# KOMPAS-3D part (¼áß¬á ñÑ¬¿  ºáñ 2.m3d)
File: created 06.04.2016 12:01:11, last saved 22.07.2016 15:59:11.
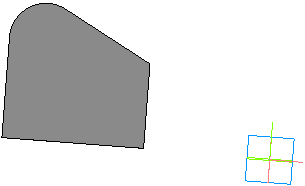
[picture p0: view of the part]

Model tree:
1. Эскиз:1
2. Операция выдавливания:1
     Толщина стенки 2 = 15; Расстояние 1 = 0.8; Расстояние 2 = 96.2519
3. Эскиз:2
4. Вырезать элемент выдавливания:1
     Толщина стенки 1 = 2; Толщина стенки 2 = 2; Расстояние 1 = 10
5. Эскиз:3
6. Вырезать элемент выдавливания:2
     Толщина стенки 1 = 2; Толщина стенки 2 = 2; Расстояние 1 = 10
7. Эскиз:4
8. Вырезать элемент выдавливания:3
     Толщина стенки 1 = 2; Толщина стенки 2 = 2; Расстояние 1 = 10.4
